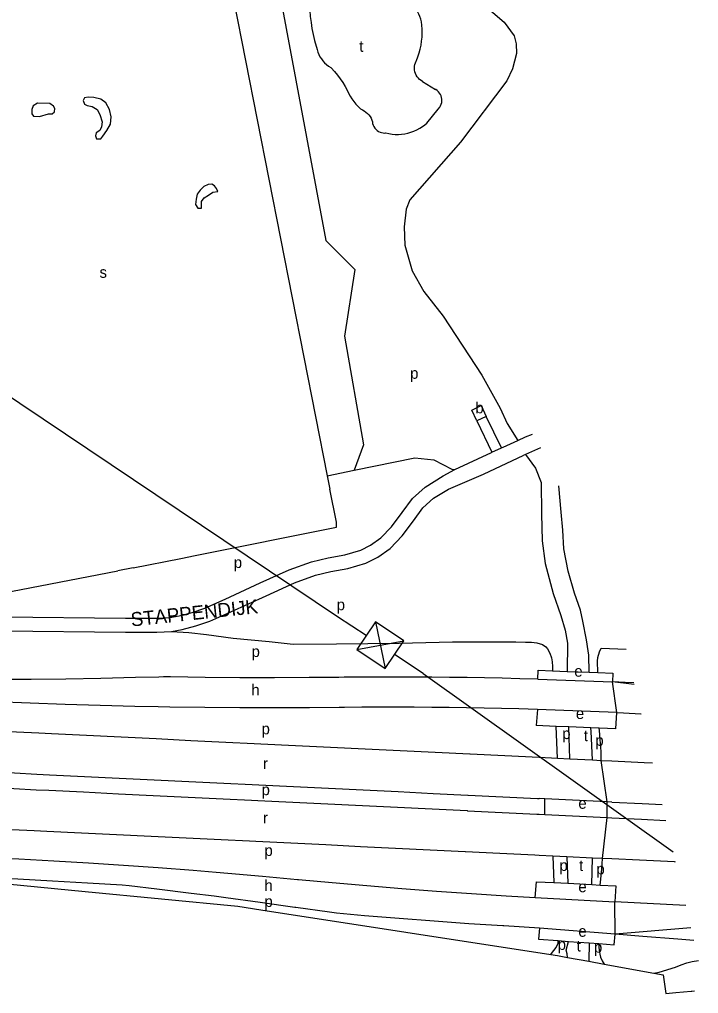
# Model space of a CAD drawing. Extents: x 160204 to 161526, y 379528 to 381793.
# Drawn here: x 161011.9 to 161255.1, y 379528.5 to 379877.4 of the extents above; entities that cross this region are included whole.
import ezdxf

# ---------------------------------------------------------------- set-up
doc = ezdxf.new("R2010")
doc.units = 0
for name, color, linetype in [('BLT_Basislijn', 7, 'Continuous'), ('BLT_Bebouwing', 7, 'Continuous'), ('BLT_Centroide', 7, 'Continuous'), ('BLT_Gemeentegrens', 7, 'Continuous'), ('BLT_Hoogspanningsmast_en_leidingen', 7, 'Continuous'), ('BLT_Straatnaam', 7, 'Continuous'), ('BLT_Vlakafsluiter', 7, 'Continuous')]:
    doc.layers.add(name, color=color, linetype=linetype)

msp = doc.modelspace()

# ---------------------------------------------------------------- linework, layer by layer
at = {"layer": 'BLT_Basislijn'}
for p, q in [((161156.3, 379855.22), (161160.92, 379852.36)), ((161184.54, 379723.94), (161179.1, 379735.18)), ((161175.73, 379733.6), (161181.12, 379722.42)), ((161181.12, 379722.42), (161184.54, 379723.94)), ((161198.56, 379724), (161193.14, 379721.61)), ((161193.14, 379721.61), (161192.58, 379721.36)), ((161122.15, 379713.93), (161131.8, 379715.9)), ((161122.15, 379713.93), (161123.11, 379709.09)), ((161069.73, 379684.36), (161074.87, 379685.38)), ((161052.59, 379681), (161069.73, 379684.36)), ((161052.59, 379681), (161047.14, 379679.9)), ((161197.57, 379641.04), (161224.33, 379640.1)), ((161225.89, 379629.15), (161197.42, 379630.24)), ((161204.06, 379624.16), (161196.98, 379624.44)), ((161208.62, 379623.98), (161204.06, 379624.16)), ((161216.49, 379623.66), (161208.62, 379623.98)), ((161219.52, 379623.54), (161216.49, 379623.66)), ((161225.45, 379623.31), (161219.52, 379623.54)), ((161198.02, 379613.08), (161204.55, 379612.76)), ((161204.55, 379612.76), (161209.05, 379612.55)), ((161209.05, 379612.55), (161217.18, 379612.15)), ((161217.18, 379612.15), (161220.18, 379612)), ((161220.18, 379612), (161224.06, 379611.81)), ((161200.09, 379598.21), (161198.05, 379598.31)), ((161200.09, 379592.61), (161200.09, 379598.21)), ((161222.34, 379597.13), (161200.09, 379598.21)), ((161224.1, 379597.04), (161222.34, 379597.13)), ((161222.34, 379591.52), (161222.34, 379597.13)), ((161198, 379592.71), (161200.09, 379592.61)), ((161200.09, 379592.61), (161222.34, 379591.52)), ((161222.34, 379591.52), (161224.05, 379591.44)), ((161202.94, 379577.7), (161198.04, 379577.94)), ((161207.93, 379577.46), (161202.94, 379577.7)), ((161217.07, 379577.01), (161207.93, 379577.46)), ((161220.74, 379576.83), (161217.07, 379577.01)), ((161224.07, 379576.67), (161220.74, 379576.83)), ((161197.05, 379568.53), (161203.25, 379568.21)), ((161203.25, 379568.21), (161208.3, 379567.94)), ((161208.3, 379567.94), (161216.89, 379567.48)), ((161216.89, 379567.48), (161219.89, 379567.33)), ((161219.89, 379567.33), (161225.52, 379567.03)), ((161196.61, 379562.8), (161225.09, 379561.35)), ((161225.19, 379549.69), (161198.12, 379551.84))]:
    msp.add_line(p, q, dxfattribs=at)
for points in [[(161089.98, 379965.09), (161092.01, 379944.76), (161104.98, 379922.95), (161104.46, 379917.75), (161103.95, 379892.82), (161121.59, 379798.29), (161131.97, 379787.9), (161128.34, 379764.01), (161135.09, 379725.05), (161131.8, 379715.9)], [(161095.53, 379898.51), (161097.96, 379886.33), (161088.72, 379883.92), (161122.15, 379713.93)], [(161115.89, 379889.28), (161115.77, 379887.11), (161115.72, 379884.95), (161115.75, 379882.78), (161115.87, 379880.61), (161116.06, 379878.46), (161116.33, 379876.3), (161116.68, 379874.17), (161117.12, 379872.04), (161117.62, 379869.93), (161118.21, 379867.85), (161118.31, 379867.53)], [(161170.11, 379889.75), (161185.51, 379876.4), (161189.09, 379871.61), (161189.83, 379868.74), (161189.92, 379865.27), (161188.53, 379859.79), (161186.45, 379855.49), (161169.85, 379833.42), (161151.75, 379812.76), (161150.42, 379809.47), (161149.7, 379803.08), (161149.97, 379796.52), (161152.55, 379787.37), (161156.69, 379779.91), (161163.71, 379771.17), (161177.51, 379750), (161184.09, 379738.13)], [(161155.86, 379876.53), (161155.62, 379877.5), (161155.3, 379878.45), (161154.91, 379879.37), (161154.44, 379880.26), (161153.91, 379881.1), (161153.31, 379881.9), (161152.64, 379882.65), (161151.92, 379883.34), (161151.15, 379883.97), (161150.33, 379884.54), (161149.46, 379885.04), (161148.56, 379885.48), (161148.4, 379885.54)], [(160959.88, 379880.87), (160983.6, 379762), (161001.22, 379671.83), (161001.95, 379671.12), (161047.14, 379679.9)], [(161154.11, 379862.69), (161154.63, 379864.04), (161155.07, 379865.42), (161155.44, 379866.81), (161155.73, 379868.23), (161155.95, 379869.66), (161156.08, 379871.1), (161156.13, 379872.54), (161156.11, 379873.99), (161156, 379875.43), (161155.86, 379876.53)], [(161118.31, 379867.53), (161118.5, 379866.62), (161118.77, 379865.74), (161119.12, 379864.89), (161119.54, 379864.07), (161120.03, 379863.29), (161120.59, 379862.55), (161121.2, 379861.87), (161121.88, 379861.24), (161122.61, 379860.67), (161123.38, 379860.17), (161123.58, 379860.05)], [(161123.58, 379860.05), (161124.71, 379858.81), (161125.78, 379857.52), (161126.79, 379856.18), (161127.74, 379854.79), (161128.62, 379853.35), (161129.29, 379852.14)], [(161156.3, 379855.22), (161155.74, 379855.55), (161155.22, 379855.95), (161154.76, 379856.42), (161154.35, 379856.93), (161154.01, 379857.49), (161153.74, 379858.09), (161153.54, 379858.71), (161153.42, 379859.36), (161153.38, 379860.01), (161153.43, 379860.66), (161153.55, 379861.31), (161153.74, 379861.93), (161154.02, 379862.53), (161154.11, 379862.69)], [(161129.29, 379852.14), (161129.77, 379851.05), (161130.32, 379849.99), (161130.95, 379848.97), (161131.63, 379847.99), (161132.39, 379847.07), (161133.2, 379846.19), (161134.07, 379845.37)], [(161162.45, 379845.99), (161162.75, 379846.51), (161162.97, 379847.07), (161163.12, 379847.65), (161163.18, 379848.24), (161163.17, 379848.84), (161163.08, 379849.44), (161162.91, 379850.01), (161162.67, 379850.56), (161162.35, 379851.07), (161161.97, 379851.53), (161161.53, 379851.94), (161161.04, 379852.29), (161160.92, 379852.36)], [(161157.84, 379840.28), (161159.89, 379842.74), (161161.88, 379845.25), (161162.45, 379845.99)], [(161134.07, 379845.37), (161134.79, 379845.05), (161135.42, 379844.69), (161136.02, 379844.27), (161136.56, 379843.78), (161137.04, 379843.24), (161137.46, 379842.65), (161137.82, 379842.01), (161138.1, 379841.34), (161138.29, 379840.72)], [(161138.29, 379840.72), (161138.4, 379840.13), (161138.58, 379839.56), (161138.84, 379839.02), (161139.17, 379838.52), (161139.56, 379838.07), (161140.01, 379837.67), (161140.51, 379837.34), (161141.05, 379837.08), (161141.61, 379836.89), (161142.2, 379836.78), (161142.8, 379836.74), (161143.12, 379836.76)], [(161143.12, 379836.76), (161144.24, 379836.52), (161145.37, 379836.36), (161146.51, 379836.27), (161147.65, 379836.27), (161148.79, 379836.34), (161149.92, 379836.5), (161151.03, 379836.73), (161152.13, 379837.04), (161153.2, 379837.43), (161154.24, 379837.89), (161155.25, 379838.43), (161156.22, 379839.03), (161157.14, 379839.7), (161157.84, 379840.28)], [(161184.09, 379738.13), (161186.58, 379732.69), (161190.44, 379726.63)], [(161190.44, 379726.63), (161193.17, 379727.93), (161195.61, 379728.83)], [(161184.54, 379723.94), (161185.17, 379724.22), (161190.44, 379726.63)], [(161131.8, 379715.9), (161153.51, 379720.33), (161160.29, 379719.67), (161166.71, 379716.36), (161167.82, 379716.23)], [(161165.55, 379709.19), (161178.07, 379714.55), (161192.58, 379721.36)], [(161167.82, 379716.23), (161180.9, 379722.33), (161181.12, 379722.42)], [(161193.14, 379721.61), (161196.68, 379716.64), (161198.7, 379711.49)], [(161108.55, 379680.23), (161116.46, 379683.17), (161122.44, 379684.56), (161128.4, 379685.63), (161134.14, 379687.28), (161137.63, 379689.1), (161141.38, 379691.71), (161145.12, 379695.69), (161148.96, 379700.75), (161152.62, 379705.8), (161157.25, 379709.88), (161163.69, 379713.93), (161167.82, 379716.23)], [(161198.7, 379711.49), (161198.86, 379700.36), (161199.05, 379690.65), (161200.15, 379682.48), (161203.09, 379671.78), (161205.83, 379663.86), (161207.28, 379658.69), (161208.2, 379653.95), (161208.04, 379643.87)], [(161215.9, 379643.55), (161215.79, 379649.71), (161215.6, 379651.22), (161214.96, 379655.22), (161213.67, 379661.8), (161212.81, 379665.74), (161210.71, 379671.88), (161208.42, 379679.75), (161206.84, 379687.83), (161206.56, 379694.43), (161205.92, 379700.93), (161205.1, 379710.37)], [(161074.87, 379685.38), (161125.41, 379695.48), (161125.41, 379697.37), (161123.11, 379709.09)], [(161110.45, 379675.6), (161117.9, 379678.37), (161123.45, 379679.66), (161129.54, 379680.76), (161136.01, 379682.62), (161140.22, 379684.82), (161144.66, 379687.9), (161148.95, 379692.45), (161152.98, 379697.77), (161156.34, 379702.42), (161160.25, 379705.87), (161165.55, 379709.19)], [(160975.53, 379663.75), (161005.65, 379663.43), (161049.95, 379662.91), (161061.02, 379662.97), (161065.81, 379663.17), (161069.15, 379663.77), (161073.72, 379664.97), (161078.31, 379666.46), (161085.6, 379669.78), (161098.15, 379675.54), (161108.55, 379680.23)], [(161066.36, 379658.19), (161070.23, 379658.89), (161075.13, 379660.17), (161080.13, 379661.8), (161087.68, 379665.23), (161100.22, 379670.99), (161110.45, 379675.6)], [(160996.04, 379658.53), (161005.59, 379658.43), (161049.93, 379657.91), (161061.14, 379657.97), (161066.36, 379658.19)], [(161066.36, 379658.19), (161072.55, 379657.85), (161078.96, 379657.09), (161088.49, 379655.8), (161094.95, 379655.16), (161101.3, 379654.58), (161109.91, 379653.61), (161125.45, 379653.73), (161147.87, 379653.92), (161167.01, 379654.42), (161180.48, 379654.51), (161189.62, 379654.42), (161193.18, 379654.36), (161195.28, 379654.36), (161197.24, 379654.08), (161199.18, 379653.46), (161200.41, 379652.66), (161201, 379651.97), (161201.83, 379650.34), (161202.41, 379648.68), (161202.69, 379647.26), (161202.81, 379645.6), (161202.77, 379644.08)], [(161219.02, 379643.42), (161218.93, 379647.57), (161219.06, 379648.88), (161219.65, 379650.86), (161220.22, 379652.2), (161229.14, 379651.85)], [(161197.57, 379641.04), (161197.7, 379644.28), (161202.77, 379644.08)], [(161202.77, 379644.08), (161208.04, 379643.87)], [(161208.04, 379643.87), (161215.9, 379643.55)], [(161215.9, 379643.55), (161219.02, 379643.42)], [(161219.02, 379643.42), (161224.46, 379643.21), (161224.33, 379640.1)], [(161197.57, 379641.04), (161191.06, 379641.23), (161184.77, 379641.38), (161178.49, 379641.51), (161172.2, 379641.62), (161165.91, 379641.71), (161159.62, 379641.77), (161153.34, 379641.81), (161147.05, 379641.83), (161140.76, 379641.82), (161134.47, 379641.79), (161128.18, 379641.74), (161126.27, 379641.71), (161115.72, 379641.62), (161103.28, 379641.57), (161090.84, 379641.6), (161078.4, 379641.69), (161065.96, 379641.86), (161063.47, 379641.9), (161061.82, 379641.85), (161053.51, 379641.62), (161041.05, 379641.34), (161028.59, 379641.12), (161016.13, 379640.98), (161003.66, 379640.91)], [(161231.94, 379639.81), (161228.77, 379639.94), (161224.33, 379640.1)], [(161197.42, 379630.24), (161190.77, 379630.43), (161184.53, 379630.58), (161178.28, 379630.71), (161172.03, 379630.82), (161165.78, 379630.91), (161159.54, 379630.97), (161153.29, 379631.01), (161147.04, 379631.03), (161140.79, 379631.02), (161134.54, 379630.99), (161128.29, 379630.94), (161126.4, 379630.92), (161115.79, 379630.82), (161103.29, 379630.77), (161090.79, 379630.8), (161078.29, 379630.89), (161065.79, 379631.06), (161061.63, 379631.13), (161053.28, 379631.3), (161040.79, 379631.6), (161028.29, 379631.98), (161015.79, 379632.43), (161003.3, 379632.96)], [(161197.42, 379630.24), (161196.98, 379624.44)], [(161225.45, 379623.31), (161225.89, 379629.15)], [(161225.89, 379629.15), (161228.24, 379629.02), (161234.48, 379628.71), (161234.52, 379628.71)], [(160996.42, 379622.91), (160998.43, 379622.81), (161010.92, 379622.2), (161018.91, 379621.81), (161023.41, 379621.59), (161035.89, 379620.99), (161048.38, 379620.38), (161060.86, 379619.77), (161073.35, 379619.16), (161085.83, 379618.55), (161095.97, 379618.06), (161098.32, 379617.94), (161110.8, 379617.33), (161123.29, 379616.73), (161135.77, 379616.12), (161148.26, 379615.51), (161160.74, 379614.9), (161173.23, 379614.29), (161173.36, 379614.29), (161185.71, 379613.68), (161198.02, 379613.08)], [(161204.55, 379612.76), (161204.06, 379624.16)], [(161209.05, 379612.55), (161208.62, 379623.98)], [(161217.18, 379612.15), (161216.64, 379622.38), (161216.49, 379623.66)], [(161220.18, 379612), (161220.18, 379615.17), (161219.9, 379619.51), (161219.62, 379622.68), (161219.52, 379623.54)], [(161224.06, 379611.81), (161235.65, 379611.25), (161238.61, 379611.1)], [(160999.68, 379607.98), (161010.2, 379607.47), (161018.19, 379607.08), (161022.69, 379606.86), (161035.17, 379606.25), (161047.66, 379605.64), (161060.14, 379605.04), (161072.63, 379604.43), (161085.11, 379603.82), (161095.25, 379603.32), (161097.6, 379603.21), (161110.08, 379602.6), (161122.57, 379601.99), (161135.05, 379601.38), (161147.54, 379600.78), (161160.02, 379600.17), (161172.51, 379599.56), (161172.64, 379599.55), (161184.99, 379598.95), (161197.48, 379598.34), (161198.05, 379598.31)], [(161000.6, 379602.33), (161009.93, 379601.88), (161017.92, 379601.49), (161022.41, 379601.27), (161034.9, 379600.66), (161047.38, 379600.05), (161059.87, 379599.44), (161072.36, 379598.83), (161084.84, 379598.23), (161094.98, 379597.73), (161097.33, 379597.62), (161109.81, 379597.01), (161122.3, 379596.4), (161134.78, 379595.79), (161147.27, 379595.18), (161159.75, 379594.57), (161172.24, 379593.97), (161172.37, 379593.96), (161184.72, 379593.36), (161197.21, 379592.75), (161198, 379592.71)], [(161224.1, 379597.04), (161234.94, 379596.52), (161242.08, 379596.17)], [(161224.05, 379591.44), (161234.66, 379590.92), (161243.4, 379590.5)], [(161198.04, 379577.94), (161196.49, 379578.02), (161184, 379578.62), (161171.65, 379579.23), (161171.52, 379579.23), (161159.03, 379579.84), (161146.55, 379580.45), (161134.06, 379581.06), (161121.58, 379581.67), (161109.09, 379582.28), (161096.61, 379582.88), (161094.26, 379583), (161084.12, 379583.49), (161071.64, 379584.1), (161059.15, 379584.71), (161046.67, 379585.32), (161034.18, 379585.93), (161021.7, 379586.54), (161017.2, 379586.75), (161009.21, 379587.14), (161003.8, 379587.41)], [(161005.73, 379576.95), (161008.08, 379576.84), (161011.72, 379576.66), (161024.2, 379575.99), (161036.68, 379575.26), (161049.16, 379574.45), (161061.63, 379573.57), (161074.1, 379572.62), (161082.32, 379571.96), (161086.56, 379571.6), (161099.01, 379570.51), (161111.46, 379569.35), (161111.81, 379569.32), (161123.91, 379568.19), (161136.36, 379567.1), (161148.81, 379566.07), (161161.27, 379565.12), (161173.74, 379564.24), (161186.21, 379563.43), (161196.61, 379562.8)], [(161202.94, 379577.7), (161203.25, 379568.21)], [(161207.93, 379577.46), (161208.3, 379567.94)], [(161216.89, 379567.48), (161217.07, 379577.01)], [(161219.89, 379567.33), (161219.96, 379568.34), (161220.45, 379573.02), (161220.74, 379576.83)], [(161246.87, 379575.56), (161246.43, 379575.58), (161233.94, 379576.19), (161224.07, 379576.67)], [(161198.12, 379551.84), (161185.32, 379552.66), (161185.05, 379552.68), (161172.84, 379553.48), (161160.37, 379554.36), (161147.9, 379555.31), (161135.44, 379556.33), (161125.43, 379557.21), (161122.94, 379557.55), (161110.84, 379559.26), (161110.5, 379559.31), (161098.16, 379561.05), (161085.81, 379562.73), (161081.6, 379563.28), (161073.44, 379564.33), (161061.07, 379565.87), (161051.16, 379567.05), (161048.67, 379567.22), (161036.24, 379568.02), (161023.8, 379568.75), (161011.35, 379569.42), (161007.72, 379569.6), (161007.53, 379569.61)], [(161196.61, 379562.8), (161197.05, 379568.53)], [(161225.52, 379567.03), (161225.09, 379561.35)], [(161250.49, 379560.01), (161225.09, 379561.35)], [(161198.12, 379551.84), (161197.82, 379547.95), (161204.89, 379547.42)], [(161219.43, 379546.32), (161224.9, 379545.91), (161225.19, 379549.69)], [(161253.4, 379547.49), (161247.63, 379547.97), (161235.17, 379548.94), (161225.19, 379549.69)], [(161202.18, 379542.43), (161202.47, 379542.76), (161204.14, 379544.96), (161204.79, 379546.47), (161204.89, 379547.42)], [(161204.89, 379547.42), (161208.51, 379547.14)], [(161208.13, 379541.41), (161208.07, 379542.69), (161207.71, 379543.95), (161208.51, 379547.14)], [(161208.51, 379547.14), (161215.97, 379546.58)], [(161215.97, 379546.58), (161215.78, 379540.02)], [(161215.97, 379546.58), (161219.43, 379546.32)], [(161219.43, 379546.32), (161219.43, 379545.1), (161219.52, 379543.97), (161219.71, 379542.61), (161219.95, 379541.47), (161220.57, 379540.15), (161221.31, 379539.02)], [(161239.03, 379535.79), (161240.95, 379536.14), (161246.81, 379537.92), (161248.86, 379538.74), (161250.85, 379539.49), (161252.79, 379539.92), (161255.08, 379540.24)]]:
    msp.add_lwpolyline(points, dxfattribs=at)
for points in [[(161035.2, 379849.33), (161034.73, 379848.37), (161035.2, 379847.05), (161036.23, 379846.56), (161037.94, 379846.22), (161039.71, 379845.13), (161040.74, 379843.37), (161041.57, 379840.7), (161041.31, 379838.91), (161040.72, 379837.69), (161039.42, 379836.81), (161039.11, 379835.78), (161039.52, 379834.66), (161041.08, 379834.64), (161041.73, 379835.67), (161043.25, 379837.62), (161044.58, 379839.9), (161044.76, 379842.51), (161044.13, 379845.11), (161042.81, 379847.52), (161041.13, 379848.86), (161038.62, 379849.43), (161036.49, 379849.56)], [(161018.43, 379847.38), (161016.82, 379846.5), (161016.38, 379845.15), (161016.36, 379843.65), (161016.93, 379842.79), (161019.05, 379842.71), (161022.29, 379843.62), (161023.61, 379843.62), (161024.49, 379844.35), (161024.6, 379845.51), (161024.13, 379846.31), (161022.76, 379847.35)], [(161077.09, 379809.76), (161077.09, 379812.17), (161078.03, 379813.52), (161079.58, 379814.53), (161081.13, 379815.54), (161082.92, 379815.83), (161082.52, 379816.87), (161081.78, 379817.85), (161080.85, 379818.43), (161079.53, 379818.33), (161077.93, 379817.53), (161076.63, 379816.31), (161075.62, 379814.85), (161075.15, 379813.07), (161074.93, 379811.16), (161075.77, 379809.8)]]:
    msp.add_lwpolyline(points, close=True, dxfattribs=at)
at = {"layer": 'BLT_Bebouwing'}
msp.add_line((161179.1, 379735.18), (161175.73, 379733.6), dxfattribs=at)
msp.add_lwpolyline([(161175.73, 379733.6), (161173.9, 379737.49), (161177.28, 379739.08), (161179.1, 379735.18)], dxfattribs=at)
at = {"layer": 'BLT_Gemeentegrens'}
for points in [[(161007.45, 379567.75), (161035.45, 379565.05), (161090.09, 379559.76), (161098.34, 379558.49), (161202.18, 379542.43)], [(161202.18, 379542.43), (161204.65, 379542.05), (161208.13, 379541.41)], [(161208.13, 379541.41), (161215.78, 379540.02)], [(161215.78, 379540.02), (161221.31, 379539.02)], [(161221.31, 379539.02), (161239.03, 379535.79)], [(161239.03, 379535.79), (161242.47, 379535.17), (161243.42, 379528.46), (161246.93, 379528.79), (161252.49, 379529.31), (161252.68, 379529.33), (161253.69, 379529.42)]]:
    msp.add_lwpolyline(points, dxfattribs=at)
at = {"layer": 'BLT_Hoogspanningsmast_en_leidingen'}
for p, q in [((161125.87, 379663.46), (160886.66, 379823.88)), ((161136.06, 379656.67), (161125.87, 379663.46)), ((161139.38, 379661.66), (161142.93, 379644.9)), ((161132.74, 379651.69), (161149.57, 379654.87)), ((161156.44, 379643.09), (161146.25, 379649.88)), ((161156.44, 379643.09), (161246.03, 379579.21))]:
    msp.add_line(p, q, dxfattribs=at)
msp.add_lwpolyline([(161132.74, 379651.69), (161142.93, 379644.9), (161149.57, 379654.87), (161139.38, 379661.66)], close=True, dxfattribs=at)
at = {"layer": 'BLT_Vlakafsluiter'}
for p, q in [((161225.89, 379629.15), (161224.33, 379640.1)), ((161232.1, 379639.14), (161224.33, 379640.1)), ((161222.34, 379597.13), (161220.18, 379612)), ((161220.74, 379576.83), (161222.34, 379591.52)), ((161225.19, 379549.69), (161225.09, 379561.35)), ((161252.34, 379552.02), (161225.19, 379549.69))]:
    msp.add_line(p, q, dxfattribs=at)

# ---------------------------------------------------------------- texts
at = {"layer": 'BLT_Centroide'}
for s, p in [('t', (161133.61, 379865.84)), ('s', (161040.59, 379784.87)), ('p', (161151.83, 379748.7)), ('b', (161175.17, 379736.34)), ('p', (161088.69, 379680.91)), ('p', (161125.52, 379665.78)), ('p', (161095.05, 379649.01)), ('e', (161210.61, 379641.97)), ('h', (161094.97, 379635.23)), ('e', (161211.17, 379626.81)), ('p', (161098.63, 379621.32)), ('p', (161206.28, 379619.62)), ('t', (161213.98, 379618.87)), ('p', (161218.13, 379617.19)), ('r', (161099.13, 379608.87)), ('p', (161098.63, 379599.52)), ('e', (161212.06, 379594.65)), ('r', (161099.13, 379589.42)), ('p', (161099.66, 379577.75)), ('p', (161205.29, 379572.39)), ('t', (161212.31, 379572.34)), ('p', (161218.51, 379571.12)), ('h', (161099.63, 379565.2)), ('e', (161212.06, 379564.75)), ('p', (161099.66, 379559.48)), ('e', (161212.06, 379548.79)), ('p', (161204.65, 379544.09)), ('t', (161211.44, 379543.52)), ('p', (161217.64, 379543.11))]:
    msp.add_text(s, height=4, dxfattribs=at).set_placement(p)
at = {"layer": 'BLT_Straatnaam'}
msp.add_text('STAPPENDIJK', height=5, rotation=6.0361, dxfattribs=at).set_placement((161052.06, 379659.93))

doc.saveas('drawing.dxf')
